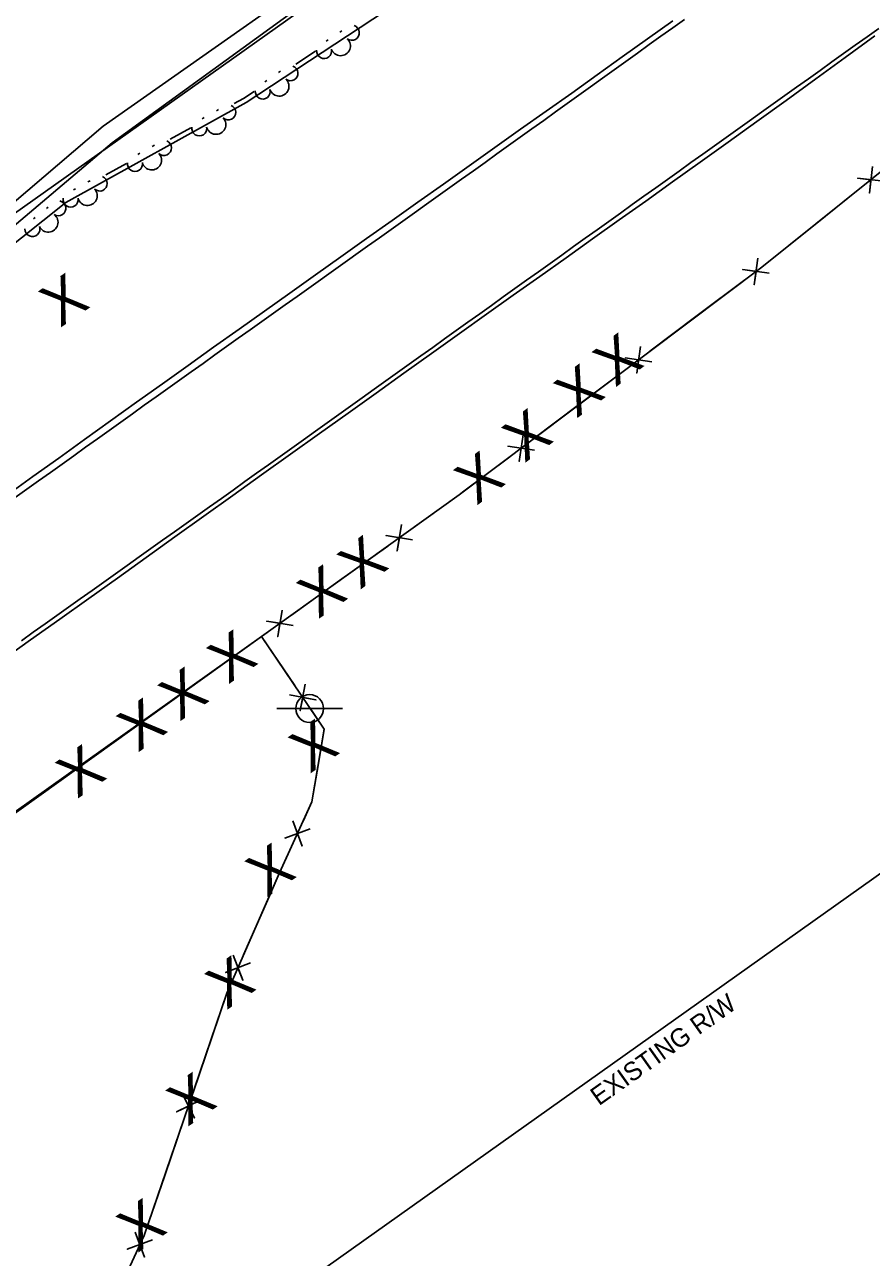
# Model space of a CAD drawing. Extents: x 1577032 to 1581865, y 611492 to 615011.
# Drawn here: x 1578332.8 to 1578479.3, y 612179.1 to 612392.5 of the extents above; entities that cross this region are included whole.
import ezdxf

# ---------------------------------------------------------------- set-up
doc = ezdxf.new("R2010")
doc.units = 0
for name, color, linetype in [('Exist Other Culture Fence Line', 7, 'Continuous'), ('Exist Right of Way Line', 7, 'Continuous'), ('Exist Right of Way Line Text', 7, 'Continuous'), ('Exist Roads EOP', 7, 'Continuous'), ('Exist Roads EOT', 7, 'Continuous'), ('Exist Utilities Telephone Pole CELL', 7, 'Continuous'), ('Exist Utilities Telephone UG FO SUE LOS B', 7, 'Continuous'), ('Exist Utilities Water UG Line SUE LOS B', 7, 'Continuous'), ('Exist Vegetation Tree CELL', 7, 'Continuous'), ('Old_Level_11', 7, 'Continuous'), ('Old_Level_8', 7, 'Continuous')]:
    doc.layers.add(name, color=color, linetype=linetype)

msp = doc.modelspace()

# ---------------------------------------------------------------- linework, layer by layer
at = {"layer": 'Exist Other Culture Fence Line'}
msp.add_line((1578035.35, 612046.03), (1578373.74, 612286.54), dxfattribs=at)
at = {"layer": 'Exist Right of Way Line'}
msp.add_line((1578304.92, 612120.6), (1580458.22, 613649.74), dxfattribs=at)
msp.add_lwpolyline([(1578124.38, 612213.06), (1579205.66, 612980.92)], dxfattribs=at)
at = {"layer": 'Exist Roads EOP'}
for points in [[(1578444.94, 612393.12), (1578440.55, 612389.98), (1578436.18, 612386.87), (1578431.81, 612383.75), (1578427.42, 612380.63), (1578423.01, 612377.5), (1578418.58, 612374.35), (1578414.13, 612371.2), (1578409.67, 612368.04), (1578405.23, 612364.88), (1578400.79, 612361.73), (1578396.35, 612358.58), (1578391.93, 612355.43), (1578387.51, 612352.28), (1578383.1, 612349.15), (1578378.69, 612346.01), (1578374.29, 612342.88), (1578369.89, 612339.76), (1578365.49, 612336.63), (1578361.06, 612333.48), (1578356.62, 612330.31), (1578352.15, 612327.11), (1578347.66, 612323.9), (1578343.17, 612320.68), (1578338.69, 612317.46), (1578334.22, 612314.25), (1578329.76, 612311.04)], [(1578328.65, 612282.32), (1578333.8, 612285.97), (1578338.88, 612289.58), (1578343.88, 612293.14), (1578348.84, 612296.68), (1578353.81, 612300.24), (1578358.8, 612303.81), (1578363.79, 612307.38), (1578368.78, 612310.96), (1578373.79, 612314.54), (1578378.8, 612318.11), (1578383.81, 612321.68), (1578388.74, 612325.2), (1578393.59, 612328.68), (1578398.39, 612332.13), (1578403.2, 612335.57), (1578408, 612338.99), (1578412.71, 612342.35), (1578417.32, 612345.63), (1578421.89, 612348.88), (1578426.47, 612352.13), (1578431.05, 612355.39), (1578435.64, 612358.66), (1578440.24, 612361.94), (1578444.88, 612365.26), (1578449.63, 612368.65), (1578454.48, 612372.12), (1578459.44, 612375.68), (1578464.51, 612379.35), (1578469.64, 612383.07), (1578474.75, 612386.79), (1578479.86, 612390.5)]]:
    msp.add_lwpolyline(points, dxfattribs=at)
at = {"layer": 'Exist Roads EOT'}
for points in [[(1578446.93, 612393.36), (1578444.9, 612391.9), (1578442.87, 612390.45), (1578440.84, 612389), (1578438.82, 612387.54), (1578436.79, 612386.09), (1578434.76, 612384.63), (1578432.73, 612383.18), (1578430.7, 612381.72), (1578428.67, 612380.27), (1578426.64, 612378.81), (1578424.61, 612377.36), (1578422.58, 612375.9), (1578420.55, 612374.45), (1578418.53, 612373), (1578416.5, 612371.54), (1578414.47, 612370.09), (1578412.44, 612368.63), (1578410.41, 612367.18), (1578408.38, 612365.72), (1578406.35, 612364.27), (1578404.32, 612362.82), (1578402.29, 612361.37), (1578400.25, 612359.92), (1578398.22, 612358.47), (1578396.19, 612357.02), (1578394.15, 612355.57), (1578392.12, 612354.13), (1578381.95, 612346.88), (1578379.92, 612345.43), (1578377.88, 612343.99), (1578375.85, 612342.54), (1578373.82, 612341.09), (1578371.78, 612339.64), (1578369.75, 612338.19), (1578367.71, 612336.74), (1578365.68, 612335.3), (1578363.65, 612333.84), (1578361.62, 612332.39), (1578359.59, 612330.94), (1578357.56, 612329.49), (1578355.52, 612328.03), (1578353.49, 612326.58), (1578351.46, 612325.13), (1578349.43, 612323.68), (1578347.4, 612322.22), (1578345.37, 612320.77), (1578343.34, 612319.32), (1578341.31, 612317.86), (1578339.27, 612316.41), (1578337.24, 612314.96), (1578335.21, 612313.51), (1578333.18, 612312.05), (1578331.15, 612310.6)], [(1578332.25, 612285.84), (1578334.28, 612287.29), (1578336.32, 612288.74), (1578338.35, 612290.19), (1578340.38, 612291.64), (1578342.42, 612293.09), (1578344.45, 612294.53), (1578346.49, 612295.98), (1578348.52, 612297.43), (1578350.55, 612298.88), (1578352.59, 612300.33), (1578354.62, 612301.78), (1578356.66, 612303.23), (1578358.69, 612304.68), (1578360.72, 612306.12), (1578362.76, 612307.57), (1578364.79, 612309.02), (1578366.83, 612310.47), (1578368.86, 612311.92), (1578370.89, 612313.37), (1578372.92, 612314.82), (1578374.95, 612316.28), (1578376.99, 612317.73), (1578379.02, 612319.18), (1578381.05, 612320.63), (1578383.08, 612322.09), (1578385.11, 612323.54), (1578387.14, 612324.99), (1578389.17, 612326.44), (1578391.2, 612327.9), (1578393.23, 612329.35), (1578395.26, 612330.8), (1578397.29, 612332.25), (1578399.32, 612333.71), (1578401.35, 612335.16), (1578403.38, 612336.61), (1578405.42, 612338.06), (1578407.45, 612339.52), (1578409.48, 612340.97), (1578411.51, 612342.42), (1578413.54, 612343.87), (1578415.57, 612345.33), (1578417.6, 612346.78), (1578419.63, 612348.23), (1578421.66, 612349.69), (1578423.69, 612351.14), (1578425.72, 612352.59), (1578427.75, 612354.05), (1578429.78, 612355.5), (1578431.81, 612356.95), (1578433.84, 612358.4), (1578435.87, 612359.86), (1578437.9, 612361.31), (1578439.93, 612362.76), (1578441.96, 612364.22), (1578443.99, 612365.67), (1578446.02, 612367.12), (1578448.05, 612368.58), (1578450.08, 612370.03), (1578452.11, 612371.48), (1578454.14, 612372.93), (1578456.17, 612374.38), (1578458.2, 612375.84), (1578460.23, 612377.29), (1578462.27, 612378.74), (1578464.3, 612380.19), (1578466.33, 612381.65), (1578468.36, 612383.1), (1578470.39, 612384.55), (1578472.42, 612386), (1578474.45, 612387.45), (1578476.48, 612388.91), (1578478.51, 612390.36), (1578480.54, 612391.81)]]:
    msp.add_lwpolyline(points, dxfattribs=at)
at = {"layer": 'Exist Utilities Telephone Pole CELL'}
for p, q in [((1578376.42, 612274.1), (1578387.76, 612274.1)), ((1578382.1, 612274.1), (1578382.1, 612274.1))]:
    msp.add_line(p, q, dxfattribs=at)
msp.add_circle((1578382.1, 612274.1), 2.41, dxfattribs=at)
at = {"layer": 'Exist Utilities Telephone UG FO SUE LOS B'}
msp.add_lwpolyline([(1578195.73, 612250.34), (1578241.59, 612286.54), (1578291.86, 612328.33), (1578346.38, 612374.92), (1578396.97, 612410.49), (1578454.86, 612448.05), (1578513.8, 612486.88), (1578570.79, 612520.18), (1578660.13, 612580.57), (1578739.65, 612636.41), (1578799.35, 612673.77), (1578835.75, 612699.17), (1578865.6, 612719.98), (1578923.89, 612761.36), (1578953.65, 612786.53), (1578992.35, 612823.36), (1579016.04, 612847.4), (1579030.15, 612863.93), (1579038.32, 612877.78)], dxfattribs=at)
at = {"layer": 'Exist Utilities Water UG Line SUE LOS B'}
for p, q in [((1578347.91, 612371.98), (1578398.94, 612409.07)), ((1578293.88, 612326.25), (1578347.91, 612371.98))]:
    msp.add_line(p, q, dxfattribs=at)
at = {"layer": 'Old_Level_11'}
for points in [[(1578817.97, 612709.56), (1578809.14, 612701.87), (1578766.25, 612667.71), (1578729.93, 612641.39), (1578711, 612629.29), (1578666.02, 612599.72), (1578626.26, 612569.19), (1578597.37, 612539.75), (1578558.5, 612501.79), (1578537.75, 612486.32), (1578502.24, 612463.66), (1578465.91, 612440.49), (1578423.86, 612413.78), (1578371.1, 612378.99), (1578339.9, 612361.7)], [(1578339.9, 612361.7), (1578204.34, 612253.64), (1578172.23, 612297.97), (1578158.43, 612324.06), (1578147.64, 612359.64), (1578139.86, 612379.18), (1578137.69, 612395.49), (1578121.33, 612436.75), (1578108.17, 612462.31)], [(1578385.29, 612389.82), (1578384.95, 612389.59)], [(1578387.69, 612391.4), (1578387.34, 612391.17)], [(1578383.12, 612387.9), (1578379.69, 612385.64)], [(1578377.07, 612384.4), (1578376.73, 612384.17)], [(1578372.5, 612380.9), (1578370.68, 612379.69), (1578369.06, 612378.8)], [(1578374.67, 612382.82), (1578374.33, 612382.59)], [(1578366.35, 612377.76), (1578365.99, 612377.56)], [(1578361.53, 612374.62), (1578357.94, 612372.63)], [(1578363.84, 612376.37), (1578363.48, 612376.17)], [(1578352.72, 612370.21), (1578352.36, 612370.01)], [(1578355.23, 612371.6), (1578354.87, 612371.4)], [(1578350.41, 612368.46), (1578346.82, 612366.47)], [(1578341.6, 612364.05), (1578341.24, 612363.85)], [(1578344.11, 612365.44), (1578343.75, 612365.24)], [(1578336.89, 612360.88), (1578336.57, 612360.62)], [(1578334.64, 612359.08), (1578334.32, 612358.83)]]:
    msp.add_lwpolyline(points, dxfattribs=at)
for centre, radius, start, end in [((1578389.39, 612391.05), 1.3, 231.8379, 72.6345), ((1578387.45, 612388.78), 1.69, 199.3667, 47.4392), ((1578384.6, 612387.89), 1.3, 174.1715, 14.968), ((1578378.78, 612384.05), 1.3, 231.8379, 72.6345), ((1578376.83, 612381.78), 1.69, 199.3667, 47.4392), ((1578373.98, 612380.89), 1.3, 174.1715, 14.968), ((1578368.02, 612377.28), 1.3, 227.4228, 68.2193), ((1578363, 612374.5), 1.3, 169.7563, 10.5529), ((1578365.91, 612375.17), 1.69, 194.9516, 43.0241), ((1578356.9, 612371.12), 1.3, 227.4228, 68.2193), ((1578354.79, 612369.01), 1.69, 194.9516, 43.0241), ((1578351.88, 612368.34), 1.3, 169.7563, 10.5529), ((1578345.78, 612364.96), 1.3, 227.4228, 68.2193), ((1578343.67, 612362.85), 1.69, 194.9516, 43.0241), ((1578338.62, 612360.68), 1.3, 236.9963, 77.7929), ((1578340.76, 612362.18), 1.3, 169.7563, 10.5529), ((1578336.88, 612358.25), 1.69, 204.5251, 52.5976), ((1578334.13, 612357.1), 1.3, 179.3299, 20.1264)]:
    msp.add_arc(centre, radius, start, end, dxfattribs=at)
at = {"layer": 'Old_Level_8'}
for points in [[(1578881.9, 612391.29), (1578838.85, 612603.7), (1578768.9, 612557.39), (1578685.72, 612501.63), (1578621.8, 612457.59), (1578581.41, 612434.88), (1578539.94, 612410.43), (1578493.3, 612376.95), (1578460.29, 612350.49), (1578407.94, 612311.07)], [(1578479.43, 612367.93), (1578478.92, 612363.32), (1578479.17, 612365.63), (1578476.87, 612365.88), (1578481.48, 612365.37)], [(1578477.25, 612364.09), (1578469.25, 612357.67)], [(1578469.25, 612357.67), (1578461.25, 612351.26)], [(1578459.64, 612352.05), (1578458.99, 612347.45), (1578459.31, 612349.75), (1578457.01, 612350.08), (1578461.61, 612349.43)], [(1578457.35, 612348.27), (1578449.15, 612342.11)], [(1578449.15, 612342.11), (1578440.96, 612335.94)], [(1578439.32, 612336.76), (1578438.67, 612332.16), (1578439, 612334.46), (1578436.7, 612334.78), (1578441.3, 612334.13)], [(1578437.03, 612332.98), (1578428.84, 612326.81)], [(1578428.84, 612326.81), (1578420.65, 612320.64)], [(1578419.01, 612321.46), (1578418.36, 612316.87), (1578418.69, 612319.16), (1578416.39, 612319.49), (1578420.98, 612318.84)], [(1578416.72, 612317.68), (1578408.53, 612311.52)], [(1578407.94, 612311.07), (1578098.35, 612089.04)], [(1578407.94, 612311.07), (1578399.61, 612305.1)], [(1578408.53, 612311.52), (1578407.94, 612311.07)], [(1578397.99, 612305.95), (1578397.23, 612301.38), (1578397.61, 612303.66), (1578395.32, 612304.04), (1578399.9, 612303.29)], [(1578395.61, 612302.23), (1578387.28, 612296.25)], [(1578387.28, 612296.25), (1578378.95, 612290.28)], [(1578377.32, 612291.14), (1578376.57, 612286.56), (1578376.95, 612288.85), (1578374.66, 612289.22), (1578379.24, 612288.47)], [(1578374.95, 612287.41), (1578366.62, 612281.44)], [(1578373.74, 612286.54), (1578384.63, 612270.55), (1578382.5, 612257.95), (1578376.86, 612245.65), (1578367.79, 612224.86), (1578360.36, 612203), (1578353.46, 612182.91), (1578343.75, 612161.77), (1578330.13, 612139.03), (1578312.35, 612107.45), (1578297.78, 612075.84), (1578288.7, 612046.49), (1578279.68, 612017.22), (1578273.63, 611996.6), (1578269, 611971.64), (1578266.74, 611958.58), (1578264.59, 611943.91), (1578264.39, 611931.48)], [(1578373.74, 612286.54), (1578379.51, 612278.07)], [(1578378.61, 612276.47), (1578383.17, 612275.6), (1578380.89, 612276.04), (1578380.46, 612273.76), (1578381.32, 612278.31)], [(1578382.28, 612274), (1578384.63, 612270.55), (1578383.62, 612264.56)], [(1578383.62, 612264.56), (1578382.5, 612257.95), (1578381.02, 612254.72)], [(1578379.19, 612254.66), (1578380.8, 612250.31), (1578379.99, 612252.49), (1578377.82, 612251.68), (1578382.17, 612253.29)], [(1578378.97, 612250.25), (1578376.86, 612245.65), (1578374.78, 612240.89)], [(1578374.78, 612240.89), (1578370.68, 612231.49)], [(1578368.85, 612231.4), (1578370.54, 612227.08), (1578369.7, 612229.24), (1578367.54, 612228.39), (1578371.86, 612230.09)], [(1578368.71, 612226.98), (1578367.79, 612224.86), (1578365.23, 612217.35)], [(1578365.23, 612217.35), (1578361.94, 612207.64)], [(1578360.12, 612207.39), (1578362.17, 612203.23), (1578361.15, 612205.31), (1578359.07, 612204.28), (1578363.23, 612206.33)], [(1578360.35, 612202.98), (1578357.02, 612193.28)], [(1578357.02, 612193.28), (1578353.69, 612183.59)], [(1578351.92, 612183.5), (1578353.54, 612179.15), (1578352.73, 612181.32), (1578350.55, 612180.52), (1578354.9, 612182.13)]]:
    msp.add_lwpolyline(points, dxfattribs=at)

# ---------------------------------------------------------------- texts
at = {"layer": 'Exist Right of Way Line Text'}
msp.add_text('EXISTING R/W', height=3.2, rotation=35.38, dxfattribs=at).set_placement((1578432.13, 612205.26))
at = {"layer": 'Exist Vegetation Tree CELL'}
for rotation, p in [(34.4517, (1578338.91, 612339.95)), (36.4985, (1578434.9, 612329.6)), (36.4985, (1578428.2, 612324.23)), (36.4985, (1578419.22, 612316.51)), (36.4985, (1578410.93, 612309.16)), (36.4985, (1578390.75, 612294.58)), (34.4517, (1578383.51, 612289.51)), (34.4517, (1578367.98, 612278.24)), (34.4517, (1578359.54, 612271.79)), (34.4517, (1578352.36, 612266.45)), (34.4517, (1578382.11, 612262.78)), (34.4517, (1578341.82, 612258.39)), (34.4517, (1578374.61, 612241.34)), (34.4517, (1578367.65, 612221.84)), (34.4517, (1578360.93, 612201.66)), (34.4517, (1578352.3, 612179.84))]:
    msp.add_text('X', height=7.38, rotation=rotation, dxfattribs=at).set_placement(p)

doc.saveas('drawing.dxf')
